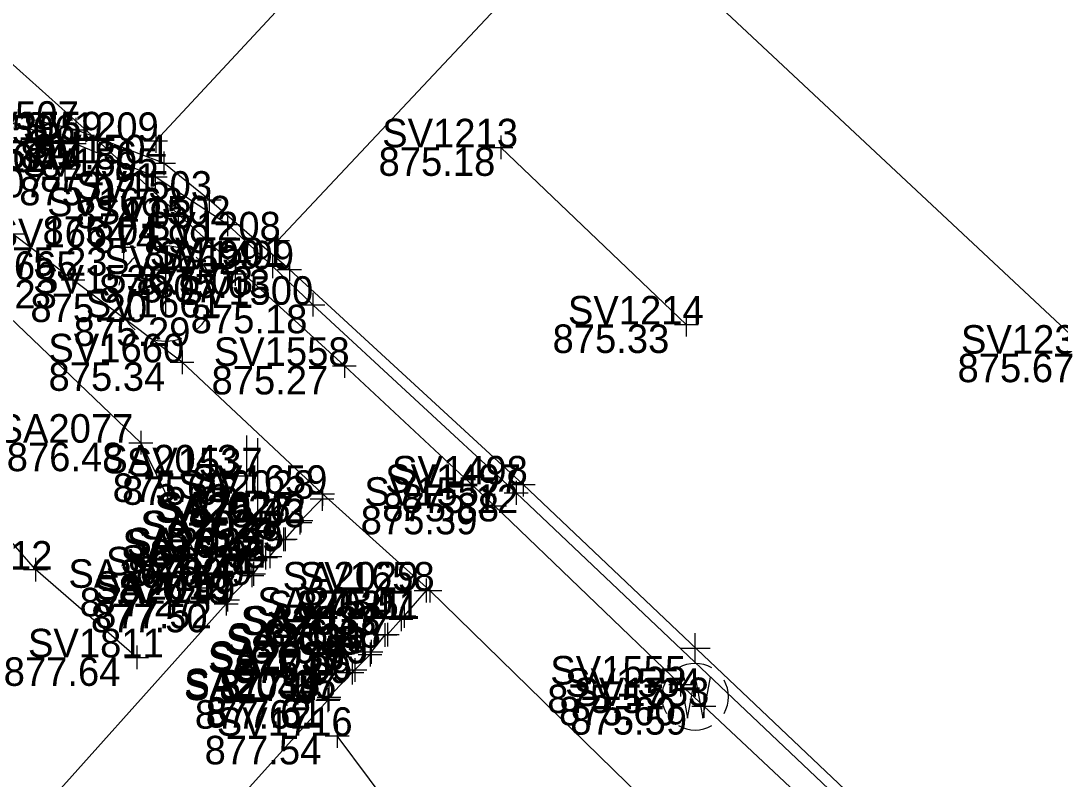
# Model space of a CAD drawing. Extents: x 1480001 to 1480402, y 379235 to 379603.
# Drawn here: x 1480179.61 to 1480223.31, y 379358.27 to 379390.17 of the extents above; entities that cross this region are included whole.
import ezdxf

# ---------------------------------------------------------------- set-up
doc = ezdxf.new("R2010")
doc.units = 0
for name, color, linetype in [('Default', 7, 'Continuous'), ('PM_P_CL_Double_Solid', 7, 'Continuous'), ('PM_X_Crosswalk', 7, 'Continuous'), ('PM_X_Lane_Line', 7, 'Continuous'), ('PV_X_Curb', 7, 'Continuous'), ('PV_X_Steps', 7, 'Continuous'), ('PV_X_Walk', 7, 'Continuous'), ('SN_X_Public', 7, 'Continuous'), ('SV_X_Break_Lines', 7, 'Continuous'), ('SV_X_Shot_Marker', 7, 'Continuous'), ('SV_X_Text_Elevation', 7, 'Continuous'), ('SV_X_Text_Name', 7, 'Continuous'), ('UT_X_Telecom_Cells', 7, 'Continuous'), ('UT_X_Water', 7, 'Continuous'), ('UT_X_Water_Cells', 7, 'Continuous')]:
    doc.layers.add(name, color=color, linetype=linetype)

msp = doc.modelspace()

# ---------------------------------------------------------------- linework, layer by layer
at = {"layer": 'Default'}
msp.add_line((1480189.091, 379371.129), (1480189.091, 379371.129), dxfattribs=at)
at = {"layer": 'PM_P_CL_Double_Solid'}
msp.add_lwpolyline([(1480349.171, 379259.048), (1480326.954, 379280.06), (1480305.568, 379299.916), (1480284.393, 379319.578), (1480263.301, 379339.268), (1480242.575, 379359.213), (1480224.612, 379376.165), (1480208.191, 379391.527)], dxfattribs=at)
at = {"layer": 'PM_X_Crosswalk'}
for p, q in [((1480185.279, 379385.114), (1480212.329, 379414.193)), ((1480217.07, 379409.327), (1480190.411, 379380.931))]:
    msp.add_line(p, q, dxfattribs=at)
at = {"layer": 'PM_X_Lane_Line'}
msp.add_line((1480199.787, 379384.844), (1480207.586, 379377.394), dxfattribs=at)
at = {"layer": 'PV_X_Curb'}
for points in [[(1480233.83, 379339.39), (1480215.875, 379356.288), (1480200.731, 379370.664), (1480190.903, 379379.712), (1480187.53, 379382.642), (1480185.615, 379384.173), (1480181.928, 379385.583), (1480179.411, 379386.173), (1480174.793, 379387.235), (1480172.715, 379387.432), (1480170.332, 379387.359), (1480168.876, 379387.382), (1480166.808, 379386.944), (1480164.881, 379386.368), (1480162.883, 379385.531), (1480159.898, 379383.853), (1480158.052, 379382.754), (1480156.183, 379381.403), (1480155.05, 379380.342)], [(1480233.297, 379339.4), (1480215.447, 379356.074), (1480200.436, 379370.31), (1480191.889, 379378.223), (1480190.185, 379379.842), (1480188.303, 379381.604), (1480185.259, 379383.605), (1480181.861, 379385.001), (1480179.101, 379385.902), (1480178.705, 379386.045), (1480178.118, 379386.223), (1480177.29, 379386.43), (1480176.688, 379386.511), (1480174.95, 379386.851), (1480173.419, 379387.005), (1480171.202, 379387.128), (1480169.933, 379386.966), (1480168.123, 379386.781), (1480166.87, 379386.446), (1480165.488, 379386.008), (1480163.201, 379385.04), (1480160.165, 379383.332), (1480157.23, 379381.331), (1480156.058, 379380.439)]]:
    msp.add_lwpolyline(points, dxfattribs=at)
at = {"layer": 'PV_X_Steps'}
for points in [[(1480188.304, 379365.814), (1480189.319, 379366.84), (1480189.396, 379366.905), (1480189.901, 379367.585), (1480190.075, 379367.64), (1480190.654, 379368.354), (1480190.724, 379368.36), (1480191.341, 379369.059), (1480191.387, 379369.144), (1480192.271, 379370.061)], [(1480196.652, 379366.206), (1480195.721, 379365.137), (1480195.592, 379364.998), (1480195.02, 379364.348), (1480194.917, 379364.334), (1480194.331, 379363.623), (1480194.29, 379363.51), (1480193.657, 379362.863), (1480193.534, 379362.753), (1480192.563, 379361.715)]]:
    msp.add_lwpolyline(points, dxfattribs=at)
at = {"layer": 'PV_X_Walk'}
msp.add_line((1480192.551, 379361.638), (1480192.551, 379361.638), dxfattribs=at)
for points in [[(1480327.959, 379242.083), (1480313.163, 379256.356), (1480297.576, 379270.674), (1480283.951, 379284.205), (1480267.344, 379299.69), (1480258.509, 379307.782), (1480244.036, 379321.372), (1480229.243, 379335.021), (1480213.414, 379349.982), (1480196.806, 379366.202), (1480192.296, 379370.271), (1480186.385, 379375.802), (1480181.8, 379379.27), (1480179.258, 379381.212), (1480177.445, 379382.131), (1480174.921, 379382.868), (1480171.98, 379383.537), (1480169.491, 379383.403), (1480167.014, 379382.902), (1480162.891, 379380.83), (1480161.298, 379379.691), (1480158.915, 379377.808)], [(1480108.223, 379298.793), (1480126.311, 379318.205), (1480145.385, 379338.742), (1480160.312, 379354.639), (1480170.225, 379345.82), (1480179.011, 379355.326), (1480188.24, 379365.647)], [(1480192.517, 379361.591), (1480182.642, 379350.612), (1480174.641, 379341.817)]]:
    msp.add_lwpolyline(points, dxfattribs=at)
at = {"layer": 'SN_X_Public'}
for p, q in [((1480189.091, 379372.729), (1480189.091, 379369.529)), ((1480189.563, 379372.607), (1480189.563, 379369.407)), ((1480189.091, 379371.129), (1480187.491, 379371.129)), ((1480189.563, 379371.007), (1480187.963, 379371.007))]:
    msp.add_line(p, q, dxfattribs=at)
at = {"layer": 'SV_X_Break_Lines'}
for points in [[(1480109.136, 379300.654), (1480103.503, 379307.396), (1480120.541, 379324.578), (1480124.787, 379337.805), (1480137.007, 379352.173), (1480144.932, 379357.565), (1480149.611, 379361.971), (1480150.052, 379364.189), (1480148.777, 379365.458), (1480163.875, 379379.601), (1480168.818, 379380.654), (1480172.802, 379381.332), (1480178.472, 379378.317), (1480184.655, 379372.421), (1480187.645, 379366.317)], [(1480184.481, 379363.392), (1480180.224, 379367.084), (1480176.21, 379371.695), (1480171.222, 379375.535), (1480168.077, 379375.239), (1480160.326, 379371.415), (1480150.91, 379361.854), (1480140.301, 379350.86), (1480130.798, 379340.93), (1480121.664, 379330.001), (1480112.679, 379319.616)], [(1480230.882, 379325.878), (1480225.522, 379331.489), (1480218.264, 379339.152), (1480211.865, 379343.732), (1480205.22, 379349.624), (1480204.187, 379352.051), (1480200.993, 379355.729), (1480195.628, 379356.44), (1480192.91, 379360.091)]]:
    msp.add_lwpolyline(points, dxfattribs=at)
at = {"layer": 'SV_X_Shot_Marker'}
for p, q in [((1480178.911, 379386.173), (1480179.911, 379386.173)), ((1480181.928, 379386.083), (1480181.928, 379385.083)), ((1480181.428, 379385.583), (1480182.428, 379385.583)), ((1480181.928, 379385.583), (1480181.928, 379385.583)), ((1480182.823, 379385.639), (1480182.823, 379384.639)), ((1480185.279, 379385.614), (1480185.279, 379384.614)), ((1480181.861, 379385.501), (1480181.861, 379384.501)), ((1480182.323, 379385.139), (1480183.323, 379385.139)), ((1480182.823, 379385.139), (1480182.823, 379385.139)), ((1480184.779, 379385.114), (1480185.779, 379385.114)), ((1480185.279, 379385.114), (1480185.279, 379385.114)), ((1480199.787, 379385.344), (1480199.787, 379384.344)), ((1480181.361, 379385.001), (1480182.361, 379385.001)), ((1480181.861, 379385.001), (1480181.861, 379385.001)), ((1480185.615, 379384.673), (1480185.615, 379383.673)), ((1480199.287, 379384.844), (1480200.287, 379384.844)), ((1480199.787, 379384.844), (1480199.787, 379384.844)), ((1480181.464, 379384.442), (1480181.464, 379383.442)), ((1480178.708, 379383.939), (1480179.708, 379383.939)), ((1480180.964, 379383.942), (1480181.964, 379383.942)), ((1480181.464, 379383.942), (1480181.464, 379383.942)), ((1480185.115, 379384.173), (1480186.115, 379384.173)), ((1480185.259, 379384.105), (1480185.259, 379383.105)), ((1480185.615, 379384.173), (1480185.615, 379384.173)), ((1480184.759, 379383.605), (1480185.759, 379383.605)), ((1480185.259, 379383.605), (1480185.259, 379383.605)), ((1480187.53, 379383.142), (1480187.53, 379382.142)), ((1480187.03, 379382.642), (1480188.03, 379382.642)), ((1480187.53, 379382.642), (1480187.53, 379382.642)), ((1480186.23, 379382.443), (1480186.23, 379381.443)), ((1480188.303, 379382.104), (1480188.303, 379381.104)), ((1480185.73, 379381.943), (1480186.73, 379381.943)), ((1480186.23, 379381.943), (1480186.23, 379381.943)), ((1480187.803, 379381.604), (1480188.803, 379381.604)), ((1480188.303, 379381.604), (1480188.303, 379381.604)), ((1480178.758, 379381.212), (1480179.758, 379381.212)), ((1480183.928, 379381.14), (1480183.928, 379380.14)), ((1480190.411, 379381.431), (1480190.411, 379380.431)), ((1480189.911, 379380.931), (1480190.911, 379380.931)), ((1480190.411, 379380.931), (1480190.411, 379380.931)), ((1480183.428, 379380.64), (1480184.428, 379380.64)), ((1480183.928, 379380.64), (1480183.928, 379380.64)), ((1480190.185, 379380.342), (1480190.185, 379379.342)), ((1480188.617, 379380.018), (1480188.617, 379379.018)), ((1480189.685, 379379.842), (1480190.685, 379379.842)), ((1480190.185, 379379.842), (1480190.185, 379379.842)), ((1480190.903, 379380.212), (1480190.903, 379379.212)), ((1480181.8, 379379.77), (1480181.8, 379378.77)), ((1480188.117, 379379.518), (1480189.117, 379379.518)), ((1480188.617, 379379.518), (1480188.617, 379379.518)), ((1480190.403, 379379.712), (1480191.403, 379379.712)), ((1480190.903, 379379.712), (1480190.903, 379379.712)), ((1480181.3, 379379.27), (1480182.3, 379379.27)), ((1480181.8, 379379.27), (1480181.8, 379379.27)), ((1480191.889, 379378.723), (1480191.889, 379377.723)), ((1480187.424, 379378.188), (1480187.424, 379377.188)), ((1480191.389, 379378.223), (1480192.389, 379378.223)), ((1480191.889, 379378.223), (1480191.889, 379378.223)), ((1480186.924, 379377.688), (1480187.924, 379377.688)), ((1480187.424, 379377.688), (1480187.424, 379377.688)), ((1480207.586, 379377.894), (1480207.586, 379376.894)), ((1480207.086, 379377.394), (1480208.086, 379377.394)), ((1480207.586, 379377.394), (1480207.586, 379377.394)), ((1480186.385, 379376.302), (1480186.385, 379375.302)), ((1480193.21, 379376.151), (1480193.21, 379375.151)), ((1480185.885, 379375.802), (1480186.885, 379375.802)), ((1480186.385, 379375.802), (1480186.385, 379375.802)), ((1480192.71, 379375.651), (1480193.71, 379375.651)), ((1480193.21, 379375.651), (1480193.21, 379375.651)), ((1480184.655, 379372.921), (1480184.655, 379371.921)), ((1480184.155, 379372.421), (1480185.155, 379372.421)), ((1480184.655, 379372.421), (1480184.655, 379372.421)), ((1480200.731, 379371.164), (1480200.731, 379370.164)), ((1480192.296, 379370.771), (1480192.296, 379369.771)), ((1480200.231, 379370.664), (1480201.231, 379370.664)), ((1480200.436, 379370.81), (1480200.436, 379369.81)), ((1480200.731, 379370.664), (1480200.731, 379370.664)), ((1480191.796, 379370.271), (1480192.796, 379370.271)), ((1480192.271, 379370.561), (1480192.271, 379369.561)), ((1480192.296, 379370.271), (1480192.296, 379370.271)), ((1480199.528, 379370.268), (1480199.528, 379369.268)), ((1480199.936, 379370.31), (1480200.936, 379370.31)), ((1480200.436, 379370.31), (1480200.436, 379370.31)), ((1480191.771, 379370.061), (1480192.771, 379370.061)), ((1480192.271, 379370.061), (1480192.271, 379370.061)), ((1480191.341, 379369.559), (1480191.341, 379368.559)), ((1480191.387, 379369.644), (1480191.387, 379368.644)), ((1480199.028, 379369.768), (1480200.028, 379369.768)), ((1480199.528, 379369.768), (1480199.528, 379369.768)), ((1480190.841, 379369.059), (1480191.841, 379369.059)), ((1480190.887, 379369.144), (1480191.887, 379369.144)), ((1480191.341, 379369.059), (1480191.341, 379369.059)), ((1480191.387, 379369.144), (1480191.387, 379369.144)), ((1480190.654, 379368.854), (1480190.654, 379367.854)), ((1480190.724, 379368.86), (1480190.724, 379367.86)), ((1480189.901, 379368.085), (1480189.901, 379367.085)), ((1480190.075, 379368.14), (1480190.075, 379367.14)), ((1480190.154, 379368.354), (1480191.154, 379368.354)), ((1480190.224, 379368.36), (1480191.224, 379368.36)), ((1480190.654, 379368.354), (1480190.654, 379368.354)), ((1480190.724, 379368.36), (1480190.724, 379368.36)), ((1480189.575, 379367.64), (1480190.575, 379367.64)), ((1480190.075, 379367.64), (1480190.075, 379367.64)), ((1480180.224, 379367.584), (1480180.224, 379366.584)), ((1480189.319, 379367.34), (1480189.319, 379366.34)), ((1480189.396, 379367.405), (1480189.396, 379366.405)), ((1480189.401, 379367.585), (1480190.401, 379367.585)), ((1480189.901, 379367.585), (1480189.901, 379367.585)), ((1480179.724, 379367.084), (1480180.724, 379367.084)), ((1480180.224, 379367.084), (1480180.224, 379367.084)), ((1480187.645, 379366.817), (1480187.645, 379365.817)), ((1480188.819, 379366.84), (1480189.819, 379366.84)), ((1480188.896, 379366.905), (1480189.896, 379366.905)), ((1480189.319, 379366.84), (1480189.319, 379366.84)), ((1480189.396, 379366.905), (1480189.396, 379366.905)), ((1480187.145, 379366.317), (1480188.145, 379366.317)), ((1480187.645, 379366.317), (1480187.645, 379366.317)), ((1480188.304, 379366.314), (1480188.304, 379365.314)), ((1480196.652, 379366.706), (1480196.652, 379365.706)), ((1480196.806, 379366.702), (1480196.806, 379365.702)), ((1480188.24, 379366.147), (1480188.24, 379365.147)), ((1480196.152, 379366.206), (1480197.152, 379366.206)), ((1480196.306, 379366.202), (1480197.306, 379366.202)), ((1480196.652, 379366.206), (1480196.652, 379366.206)), ((1480196.806, 379366.202), (1480196.806, 379366.202)), ((1480187.74, 379365.647), (1480188.74, 379365.647)), ((1480187.804, 379365.814), (1480188.804, 379365.814)), ((1480188.24, 379365.647), (1480188.24, 379365.647)), ((1480188.304, 379365.814), (1480188.304, 379365.814)), ((1480195.592, 379365.498), (1480195.592, 379364.498)), ((1480195.721, 379365.637), (1480195.721, 379364.637)), ((1480195.092, 379364.998), (1480196.092, 379364.998)), ((1480195.221, 379365.137), (1480196.221, 379365.137)), ((1480195.592, 379364.998), (1480195.592, 379364.998)), ((1480195.721, 379365.137), (1480195.721, 379365.137)), ((1480194.917, 379364.834), (1480194.917, 379363.834)), ((1480195.02, 379364.848), (1480195.02, 379363.848)), ((1480194.331, 379364.123), (1480194.331, 379363.123)), ((1480194.417, 379364.334), (1480195.417, 379364.334)), ((1480194.52, 379364.348), (1480195.52, 379364.348)), ((1480194.917, 379364.334), (1480194.917, 379364.334)), ((1480195.02, 379364.348), (1480195.02, 379364.348)), ((1480184.481, 379363.892), (1480184.481, 379362.892)), ((1480194.29, 379364.01), (1480194.29, 379363.01)), ((1480183.981, 379363.392), (1480184.981, 379363.392)), ((1480184.481, 379363.392), (1480184.481, 379363.392)), ((1480193.534, 379363.253), (1480193.534, 379362.253)), ((1480193.657, 379363.363), (1480193.657, 379362.363)), ((1480193.79, 379363.51), (1480194.79, 379363.51)), ((1480193.831, 379363.623), (1480194.831, 379363.623)), ((1480194.29, 379363.51), (1480194.29, 379363.51)), ((1480194.331, 379363.623), (1480194.331, 379363.623)), ((1480193.157, 379362.863), (1480194.157, 379362.863)), ((1480193.657, 379362.863), (1480193.657, 379362.863)), ((1480193.034, 379362.753), (1480194.034, 379362.753)), ((1480193.534, 379362.753), (1480193.534, 379362.753)), ((1480207.346, 379362.75), (1480207.346, 379361.75)), ((1480192.517, 379362.091), (1480192.517, 379361.091)), ((1480192.551, 379362.138), (1480192.551, 379361.138)), ((1480192.563, 379362.215), (1480192.563, 379361.215)), ((1480206.846, 379362.25), (1480207.846, 379362.25)), ((1480207.346, 379362.25), (1480207.346, 379362.25)), ((1480192.017, 379361.591), (1480193.017, 379361.591)), ((1480192.051, 379361.638), (1480193.051, 379361.638)), ((1480192.063, 379361.715), (1480193.063, 379361.715)), ((1480192.517, 379361.591), (1480192.517, 379361.591)), ((1480192.551, 379361.638), (1480192.551, 379361.638)), ((1480192.563, 379361.715), (1480192.563, 379361.715)), ((1480208.322, 379361.842), (1480208.322, 379360.842)), ((1480207.822, 379361.342), (1480208.822, 379361.342)), ((1480208.322, 379361.342), (1480208.322, 379361.342)), ((1480192.91, 379360.591), (1480192.91, 379359.591)), ((1480192.41, 379360.091), (1480193.41, 379360.091)), ((1480192.91, 379360.091), (1480192.91, 379360.091))]:
    msp.add_line(p, q, dxfattribs=at)
at = {"layer": 'UT_X_Telecom_Cells'}
for p, q in [((1480185.048, 379379.696), (1480186.348, 379379.696)), ((1480185.698, 379377.696), (1480185.698, 379379.696)), ((1480185.698, 379378.696), (1480185.698, 379378.696))]:
    msp.add_line(p, q, dxfattribs=at)
for start, end in [(70.0577, 110.1061), (130.0806, 170.0721), (10.0169, 50.0392), (190.0169, 230.0392), (310.0114, 350.0264), (250.0577, 290.0473)]:
    msp.add_arc((1480185.697, 379378.695), 2, start, end, dxfattribs=at)
at = {"layer": 'UT_X_Water'}
msp.add_lwpolyline([(1480225.088, 379345.601), (1480208.322, 379361.342), (1480207.346, 379362.25), (1480199.528, 379369.768), (1480193.21, 379375.651), (1480182.823, 379385.139), (1480177.927, 379389.525), (1480169.423, 379398.321), (1480161.035, 379406.189), (1480144.924, 379421.019), (1480134.739, 379430.559), (1480121.485, 379441.998), (1480113.085, 379450.369), (1480106.418, 379456.915), (1480094.539, 379467.985), (1480089.15, 379472.551), (1480086.751, 379474.713), (1480073.459, 379487.337), (1480068.123, 379493.187), (1480050.678, 379510.207), (1480044.404, 379515.873)], dxfattribs=at)
at = {"layer": 'UT_X_Water_Cells'}
for p, q in [((1480207.96, 379363.133), (1480207.96, 379364.404)), ((1480208.595, 379363.769), (1480207.323, 379363.769)), ((1480207.96, 379361.733), (1480207.96, 379361.733))]:
    msp.add_line(p, q, dxfattribs=at)
msp.add_lwpolyline([(1480207.323, 379362.553), (1480207.642, 379360.829), (1480207.96, 379362.553), (1480208.28, 379360.829), (1480208.597, 379362.553)], dxfattribs=at)
for start, end in [(60.0184, 120.0157), (150.0184, 209.9816), (330.0184, 29.9816), (239.9843, 299.9816)]:
    msp.add_arc((1480207.96, 379361.734), 1.4, start, end, dxfattribs=at)

# ---------------------------------------------------------------- texts
at = {"layer": 'SV_X_Text_Elevation'}
for s, p in [('874.81', (1480176.75, 379384.383)), ('875.05', (1480177.107, 379383.939)), ('874.86', (1480179.591, 379383.914)), ('875.07', (1480176.145, 379383.801)), ('875.18', (1480194.648, 379383.644)), ('875.07', (1480175.748, 379382.742)), ('874.91', (1480180.418, 379382.973)), ('875.07', (1480179.543, 379382.405)), ('874.93', (1480181.899, 379381.442)), ('875.04', (1480180.523, 379380.743)), ('874.99', (1480182.662, 379380.404)), ('874.99', (1480184.77, 379379.731)), ('875.23', (1480178.344, 379379.44)), ('875.03', (1480184.469, 379378.642)), ('875.07', (1480182.901, 379378.318)), ('875.03', (1480185.187, 379378.512)), ('875.23', (1480176.216, 379378.07)), ('875.20', (1480180.01, 379377.496)), ('875.18', (1480186.75, 379377.023)), ('875.29', (1480181.831, 379376.488)), ('875.33', (1480201.964, 379376.194)), ('875.67', (1480218.99, 379374.965)), ('875.34', (1480180.773, 379374.602)), ('875.27', (1480187.626, 379374.451)), ('876.48', (1480179.015, 379371.221)), ('875.65', (1480183.469, 379369.929)), ('875.66', (1480183.866, 379369.807)), ('875.12', (1480195.611, 379369.464)), ('875.42', (1480186.693, 379369.071)), ('875.38', (1480194.805, 379369.11)), ('875.33', (1480186.65, 379368.861)), ('875.39', (1480193.897, 379368.568)), ('875.99', (1480185.71, 379367.859)), ('875.45', (1480185.775, 379367.944)), ('876.45', (1480185.023, 379367.154)), ('875.94', (1480185.112, 379367.16)), ('877.00', (1480184.1, 379366.385)), ('876.49', (1480184.435, 379366.44)), ('877.49', (1480183.717, 379365.64)), ('876.97', (1480183.755, 379365.705)), ('877.27', (1480182.08, 379365.117)), ('875.47', (1480191.194, 379365.002)), ('875.51', (1480191.483, 379365.006)), ('877.50', (1480182.552, 379364.447)), ('877.52', (1480182.73, 379364.614)), ('876.08', (1480189.847, 379363.798)), ('875.57', (1480190.119, 379363.937)), ('876.49', (1480189.277, 379363.134)), ('876.05', (1480189.285, 379363.148)), ('877.64', (1480178.888, 379362.192)), ('877.09', (1480188.584, 379362.31)), ('876.56', (1480188.634, 379362.423)), ('877.05', (1480187.96, 379361.663)), ('877.57', (1480187.95, 379361.553)), ('875.57', (1480201.743, 379361.05)), ('877.62', (1480186.923, 379360.391)), ('877.61', (1480187.382, 379360.438)), ('877.61', (1480187.394, 379360.515)), ('875.60', (1480202.234, 379360.533)), ('875.59', (1480202.71, 379360.142)), ('877.54', (1480187.336, 379358.891))]:
    msp.add_text(s, height=1.2, dxfattribs=at).set_placement(p)
at = {"layer": 'SV_X_Text_Name'}
for s, p in [('SV1507', (1480176.335, 379385.583)), ('SV1506', (1480176.193, 379385.001)), ('SV1559', (1480177.334, 379385.139)), ('SV1209', (1480179.696, 379385.114)), ('SV1213', (1480194.8, 379384.844)), ('SV1670', (1480175.881, 379383.942)), ('SV1504', (1480180.032, 379384.173)), ('SV1505', (1480179.666, 379383.605)), ('SV1503', (1480181.937, 379382.642)), ('SV1663', (1480180.713, 379381.943)), ('SV1502', (1480182.72, 379381.604)), ('SV1208', (1480184.828, 379380.931)), ('SV1664', (1480178.42, 379380.64)), ('SV1662', (1480183.109, 379379.518)), ('SV1501', (1480185.026, 379379.842)), ('SV1499', (1480185.386, 379379.712)), ('SV1665', (1480176.283, 379379.27)), ('SV1536', (1480180.124, 379378.696)), ('SV1500', (1480186.192, 379378.223)), ('SV1661', (1480182.341, 379377.688)), ('SV1214', (1480202.608, 379377.394)), ('SV1235', (1480219.133, 379376.165)), ('SV1660', (1480180.764, 379375.802)), ('SV1558', (1480187.721, 379375.651)), ('SA2077', (1480178.628, 379372.421)), ('SA2043', (1480183.035, 379371.129)), ('SV1537', (1480184.065, 379371.007)), ('SV1497', (1480194.928, 379370.31)), ('SV1498', (1480195.214, 379370.664)), ('SA2028', (1480186.234, 379370.061)), ('SV1659', (1480186.788, 379370.271)), ('SV1557', (1480194.049, 379369.768)), ('SA2026', (1480185.238, 379369.059)), ('SA2027', (1480185.359, 379369.144)), ('SA2024', (1480184.636, 379368.354)), ('SA2025', (1480184.696, 379368.36)), ('SA2022', (1480183.883, 379367.585)), ('SA2023', (1480184.047, 379367.64)), ('SV1812', (1480175.227, 379367.084)), ('SA2020', (1480183.188, 379366.84)), ('SA2021', (1480183.802, 379366.905)), ('SA2078', (1480181.608, 379366.317)), ('SA2029', (1480190.615, 379366.206)), ('SV1658', (1480191.298, 379366.202)), ('SA2018', (1480182.656, 379365.647)), ('SA2019', (1480182.721, 379365.814)), ('SA2030', (1480189.552, 379365.137)), ('SA2031', (1480189.96, 379364.998)), ('SA2033', (1480188.852, 379364.334)), ('SA2032', (1480188.964, 379364.348)), ('SV1811', (1480179.909, 379363.392)), ('SA2035', (1480188.225, 379363.51)), ('SA2034', (1480188.275, 379363.623)), ('SA2037', (1480187.468, 379362.753)), ('SA2036', (1480187.516, 379362.863)), ('SV1555', (1480201.867, 379362.25)), ('SA2044', (1480186.47, 379361.591)), ('SA2039', (1480186.476, 379361.638)), ('SA2038', (1480186.488, 379361.715)), ('SV1554', (1480202.49, 379361.733)), ('SV1553', (1480202.843, 379361.342)), ('SV1716', (1480187.847, 379360.091))]:
    msp.add_text(s, height=1.2, dxfattribs=at).set_placement(p)

doc.saveas('drawing.dxf')
